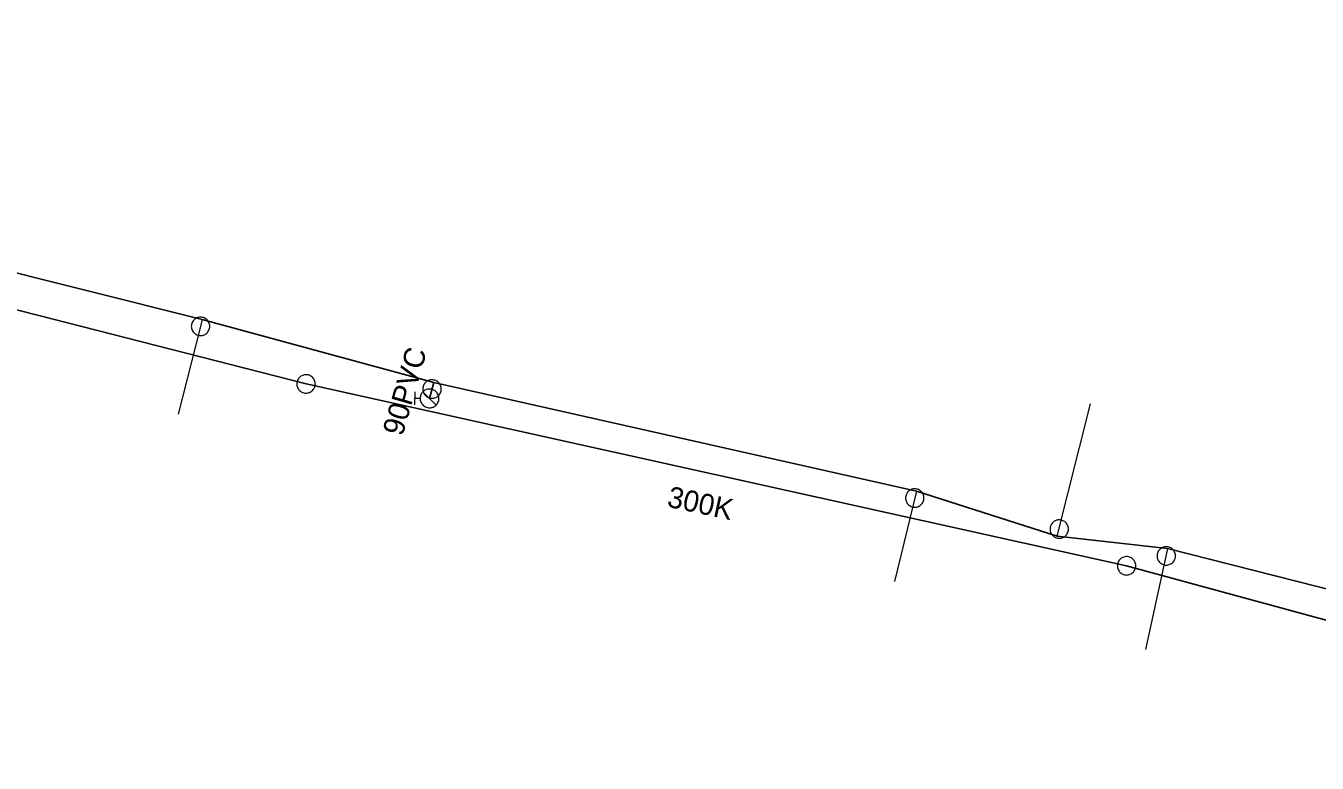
# Model space of a CAD drawing. Extents: x -741806 to -738704, y -1059275 to -1055387.
# Drawn here: x -740232.1 to -740170.7, y -1056858 to -1056822.9 of the extents above; entities that cross this region are included whole.
import ezdxf

# ---------------------------------------------------------------- set-up
doc = ezdxf.new("R2010")
doc.units = 0
doc.header["$LTSCALE"] = 0.4
for name, color, linetype, lineweight in [('2', 7, 'Continuous', 25), ('21', 7, 'Continuous', 13), ('3', 7, 'Continuous', 13), ('50', 7, 'Continuous', 13), ('51', 7, 'Continuous', 13), ('52', 7, 'Continuous', 25)]:
    doc.layers.add(name, color=color, linetype=linetype, lineweight=lineweight)
doc.layers.add('5', color=7, linetype='Continuous')
doc.layers.add('53', color=7, linetype='Continuous')

msp = doc.modelspace()

# ---------------------------------------------------------------- linework, layer by layer
at = {"layer": '2'}
msp.add_lwpolyline([(-740254.32, -1056830.86), (-740218.739, -1056839.96), (-740179.76, -1056848.6), (-740146.01, -1056857.78), (-740138.59, -1056847.639)], dxfattribs=at)
at = {"layer": '21'}
for p, q in [((-740183.054, -1056847.2), (-740181.473, -1056840.899)), ((-740189.741, -1056845.049), (-740190.787, -1056849.345)), ((-740177.82, -1056847.787), (-740178.864, -1056852.575))]:
    msp.add_line(p, q, dxfattribs=at)
msp.add_lwpolyline([(-740223.669, -1056836.908), (-740223.754, -1056837.227), (-740224.82, -1056841.397)], dxfattribs=at)
at = {"layer": '3'}
for points in [[(-740218.314, -1056840.069), (-740218.306, -1056840.024), (-740218.302, -1056839.979), (-740218.302, -1056839.932), (-740218.307, -1056839.888), (-740218.317, -1056839.843), (-740218.332, -1056839.799), (-740218.351, -1056839.758), (-740218.374, -1056839.718), (-740218.402, -1056839.682), (-740218.433, -1056839.648), (-740218.467, -1056839.618), (-740218.505, -1056839.59), (-740218.545, -1056839.569), (-740218.586, -1056839.55), (-740218.63, -1056839.537), (-740218.675, -1056839.527), (-740218.721, -1056839.524), (-740218.766, -1056839.524), (-740218.812, -1056839.529), (-740218.857, -1056839.54), (-740218.9, -1056839.554), (-740218.941, -1056839.573), (-740218.981, -1056839.597), (-740219.018, -1056839.623), (-740219.052, -1056839.655), (-740219.081, -1056839.69), (-740219.108, -1056839.726), (-740219.131, -1056839.767), (-740219.149, -1056839.809), (-740219.162, -1056839.853), (-740219.171, -1056839.897), (-740219.176, -1056839.942), (-740219.175, -1056839.989), (-740219.17, -1056840.035), (-740219.16, -1056840.078), (-740219.146, -1056840.122), (-740219.126, -1056840.163), (-740219.102, -1056840.203), (-740219.075, -1056840.239), (-740219.045, -1056840.273), (-740219.01, -1056840.303), (-740218.973, -1056840.331), (-740218.933, -1056840.353), (-740218.891, -1056840.371), (-740218.847, -1056840.384), (-740218.802, -1056840.394), (-740218.757, -1056840.398), (-740218.711, -1056840.397), (-740218.665, -1056840.392), (-740218.62, -1056840.381), (-740218.577, -1056840.367), (-740218.536, -1056840.348), (-740218.496, -1056840.324), (-740218.46, -1056840.298), (-740218.426, -1056840.266), (-740218.395, -1056840.232), (-740218.369, -1056840.195), (-740218.347, -1056840.154), (-740218.329, -1056840.112), (-740218.315, -1056840.069)], [(-740179.332, -1056848.695), (-740179.325, -1056848.65), (-740179.322, -1056848.605), (-740179.324, -1056848.558), (-740179.331, -1056848.514), (-740179.342, -1056848.469), (-740179.358, -1056848.426), (-740179.379, -1056848.385), (-740179.403, -1056848.346), (-740179.432, -1056848.311), (-740179.464, -1056848.278), (-740179.499, -1056848.249), (-740179.538, -1056848.223), (-740179.578, -1056848.203), (-740179.621, -1056848.185), (-740179.665, -1056848.173), (-740179.71, -1056848.165), (-740179.756, -1056848.163), (-740179.801, -1056848.165), (-740179.847, -1056848.172), (-740179.892, -1056848.184), (-740179.934, -1056848.2), (-740179.974, -1056848.22), (-740180.014, -1056848.245), (-740180.05, -1056848.272), (-740180.082, -1056848.305), (-740180.111, -1056848.341), (-740180.137, -1056848.378), (-740180.158, -1056848.42), (-740180.175, -1056848.462), (-740180.186, -1056848.506), (-740180.194, -1056848.551), (-740180.197, -1056848.596), (-740180.195, -1056848.643), (-740180.188, -1056848.688), (-740180.177, -1056848.732), (-740180.161, -1056848.775), (-740180.14, -1056848.816), (-740180.115, -1056848.855), (-740180.087, -1056848.89), (-740180.055, -1056848.923), (-740180.02, -1056848.952), (-740179.982, -1056848.978), (-740179.941, -1056848.999), (-740179.899, -1056849.016), (-740179.854, -1056849.028), (-740179.809, -1056849.036), (-740179.764, -1056849.039), (-740179.718, -1056849.036), (-740179.672, -1056849.029), (-740179.628, -1056849.017), (-740179.585, -1056849.001), (-740179.544, -1056848.982), (-740179.506, -1056848.956), (-740179.47, -1056848.928), (-740179.437, -1056848.896), (-740179.408, -1056848.86), (-740179.383, -1056848.823), (-740179.361, -1056848.781), (-740179.345, -1056848.739), (-740179.332, -1056848.696)]]:
    msp.add_lwpolyline(points, dxfattribs=at)
at = {"layer": '50'}
for p, q in [((-740213.572, -1056840.342), (-740213.572, -1056840.649)), ((-740213.321, -1056840.649), (-740213.572, -1056840.649)), ((-740213.572, -1056840.957), (-740213.572, -1056840.649)), ((-740212.874, -1056840.649), (-740213.186, -1056840.333)), ((-740212.874, -1056840.649), (-740212.557, -1056840.966))]:
    msp.add_line(p, q, dxfattribs=at)
msp.add_lwpolyline([(-740212.87, -1056840.205), (-740212.919, -1056840.207), (-740212.965, -1056840.212), (-740213.011, -1056840.225), (-740213.054, -1056840.242), (-740213.094, -1056840.261), (-740213.135, -1056840.288), (-740213.17, -1056840.317), (-740213.205, -1056840.35), (-740213.235, -1056840.385), (-740213.259, -1056840.425), (-740213.281, -1056840.466), (-740213.3, -1056840.509), (-740213.31, -1056840.555), (-740213.318, -1056840.601), (-740213.321, -1056840.647), (-740213.318, -1056840.693), (-740213.313, -1056840.738), (-740213.3, -1056840.784), (-740213.283, -1056840.828), (-740213.262, -1056840.871), (-740213.237, -1056840.909), (-740213.208, -1056840.946), (-740213.175, -1056840.979), (-740213.14, -1056841.008), (-740213.1, -1056841.035), (-740213.059, -1056841.057), (-740213.016, -1056841.073), (-740212.97, -1056841.087), (-740212.924, -1056841.092), (-740212.878, -1056841.098), (-740212.83, -1056841.096), (-740212.784, -1056841.088), (-740212.741, -1056841.077), (-740212.695, -1056841.061), (-740212.654, -1056841.039), (-740212.614, -1056841.015), (-740212.579, -1056840.985), (-740212.544, -1056840.953), (-740212.514, -1056840.915), (-740212.49, -1056840.877), (-740212.468, -1056840.834), (-740212.452, -1056840.791), (-740212.438, -1056840.748), (-740212.43, -1056840.699), (-740212.427, -1056840.653), (-740212.43, -1056840.607), (-740212.438, -1056840.561), (-740212.449, -1056840.515), (-740212.465, -1056840.472), (-740212.487, -1056840.429), (-740212.511, -1056840.391), (-740212.541, -1056840.353), (-740212.573, -1056840.321), (-740212.608, -1056840.291), (-740212.649, -1056840.267), (-740212.689, -1056840.243), (-740212.733, -1056840.226), (-740212.778, -1056840.216), (-740212.824, -1056840.208)], close=True, dxfattribs=at)
at = {"layer": '51'}
for points in [[(-740223.753, -1056836.79), (-740223.798, -1056836.791), (-740223.843, -1056836.798), (-740223.888, -1056836.81), (-740223.93, -1056836.826), (-740223.971, -1056836.847), (-740224.01, -1056836.872), (-740224.045, -1056836.901), (-740224.078, -1056836.933), (-740224.106, -1056836.969), (-740224.131, -1056837.007), (-740224.152, -1056837.048), (-740224.169, -1056837.091), (-740224.181, -1056837.135), (-740224.188, -1056837.18), (-740224.19, -1056837.226), (-740224.188, -1056837.272), (-740224.181, -1056837.317), (-740224.169, -1056837.361), (-740224.152, -1056837.404), (-740224.131, -1056837.445), (-740224.106, -1056837.483), (-740224.078, -1056837.519), (-740224.045, -1056837.551), (-740224.01, -1056837.58), (-740223.971, -1056837.605), (-740223.93, -1056837.626), (-740223.888, -1056837.642), (-740223.843, -1056837.654), (-740223.798, -1056837.661), (-740223.752, -1056837.665), (-740223.707, -1056837.662), (-740223.662, -1056837.655), (-740223.617, -1056837.643), (-740223.575, -1056837.627), (-740223.534, -1056837.606), (-740223.495, -1056837.581), (-740223.46, -1056837.552), (-740223.427, -1056837.52), (-740223.399, -1056837.484), (-740223.374, -1056837.446), (-740223.353, -1056837.405), (-740223.336, -1056837.362), (-740223.325, -1056837.318), (-740223.317, -1056837.273), (-740223.315, -1056837.227), (-740223.317, -1056837.181), (-740223.325, -1056837.136), (-740223.336, -1056837.092), (-740223.353, -1056837.049), (-740223.374, -1056837.008), (-740223.399, -1056836.97), (-740223.427, -1056836.934), (-740223.46, -1056836.902), (-740223.495, -1056836.873), (-740223.534, -1056836.848), (-740223.575, -1056836.827), (-740223.617, -1056836.811), (-740223.662, -1056836.799), (-740223.707, -1056836.792), (-740223.752, -1056836.79)], [(-740212.753, -1056839.766), (-740212.798, -1056839.767), (-740212.843, -1056839.774), (-740212.888, -1056839.786), (-740212.93, -1056839.802), (-740212.971, -1056839.823), (-740213.01, -1056839.848), (-740213.045, -1056839.877), (-740213.078, -1056839.909), (-740213.106, -1056839.945), (-740213.131, -1056839.983), (-740213.152, -1056840.024), (-740213.169, -1056840.067), (-740213.181, -1056840.111), (-740213.188, -1056840.156), (-740213.19, -1056840.202), (-740213.188, -1056840.248), (-740213.181, -1056840.293), (-740213.169, -1056840.337), (-740213.152, -1056840.38), (-740213.131, -1056840.421), (-740213.106, -1056840.459), (-740213.078, -1056840.495), (-740213.045, -1056840.527), (-740213.01, -1056840.556), (-740212.971, -1056840.581), (-740212.93, -1056840.602), (-740212.888, -1056840.618), (-740212.843, -1056840.63), (-740212.798, -1056840.637), (-740212.752, -1056840.641), (-740212.707, -1056840.638), (-740212.662, -1056840.631), (-740212.617, -1056840.619), (-740212.575, -1056840.603), (-740212.534, -1056840.582), (-740212.495, -1056840.557), (-740212.46, -1056840.528), (-740212.427, -1056840.496), (-740212.399, -1056840.46), (-740212.374, -1056840.422), (-740212.353, -1056840.381), (-740212.336, -1056840.338), (-740212.325, -1056840.294), (-740212.317, -1056840.249), (-740212.315, -1056840.203), (-740212.317, -1056840.157), (-740212.325, -1056840.112), (-740212.336, -1056840.068), (-740212.353, -1056840.025), (-740212.374, -1056839.984), (-740212.399, -1056839.946), (-740212.427, -1056839.91), (-740212.46, -1056839.878), (-740212.495, -1056839.849), (-740212.534, -1056839.824), (-740212.575, -1056839.803), (-740212.617, -1056839.787), (-740212.662, -1056839.775), (-740212.707, -1056839.768), (-740212.752, -1056839.766)], [(-740189.821, -1056844.944), (-740189.866, -1056844.945), (-740189.911, -1056844.952), (-740189.956, -1056844.964), (-740189.998, -1056844.98), (-740190.039, -1056845.001), (-740190.078, -1056845.026), (-740190.113, -1056845.055), (-740190.146, -1056845.087), (-740190.174, -1056845.123), (-740190.199, -1056845.161), (-740190.22, -1056845.202), (-740190.237, -1056845.245), (-740190.249, -1056845.289), (-740190.256, -1056845.334), (-740190.258, -1056845.38), (-740190.256, -1056845.426), (-740190.249, -1056845.471), (-740190.237, -1056845.515), (-740190.22, -1056845.558), (-740190.199, -1056845.599), (-740190.174, -1056845.637), (-740190.146, -1056845.673), (-740190.113, -1056845.705), (-740190.078, -1056845.734), (-740190.039, -1056845.759), (-740189.998, -1056845.78), (-740189.956, -1056845.796), (-740189.911, -1056845.808), (-740189.866, -1056845.815), (-740189.82, -1056845.819), (-740189.775, -1056845.816), (-740189.73, -1056845.809), (-740189.685, -1056845.797), (-740189.643, -1056845.781), (-740189.602, -1056845.76), (-740189.563, -1056845.735), (-740189.528, -1056845.706), (-740189.495, -1056845.674), (-740189.467, -1056845.638), (-740189.442, -1056845.6), (-740189.421, -1056845.559), (-740189.404, -1056845.516), (-740189.393, -1056845.472), (-740189.385, -1056845.427), (-740189.383, -1056845.381), (-740189.385, -1056845.335), (-740189.393, -1056845.29), (-740189.404, -1056845.246), (-740189.421, -1056845.203), (-740189.442, -1056845.162), (-740189.467, -1056845.124), (-740189.495, -1056845.088), (-740189.528, -1056845.056), (-740189.563, -1056845.027), (-740189.602, -1056845.002), (-740189.643, -1056844.981), (-740189.685, -1056844.965), (-740189.73, -1056844.953), (-740189.775, -1056844.946), (-740189.82, -1056844.944)], [(-740182.957, -1056846.421), (-740183.002, -1056846.422), (-740183.047, -1056846.429), (-740183.092, -1056846.441), (-740183.134, -1056846.457), (-740183.175, -1056846.478), (-740183.214, -1056846.503), (-740183.249, -1056846.532), (-740183.282, -1056846.564), (-740183.31, -1056846.6), (-740183.335, -1056846.638), (-740183.356, -1056846.679), (-740183.373, -1056846.722), (-740183.385, -1056846.766), (-740183.392, -1056846.811), (-740183.394, -1056846.857), (-740183.392, -1056846.903), (-740183.385, -1056846.948), (-740183.373, -1056846.992), (-740183.356, -1056847.035), (-740183.335, -1056847.076), (-740183.31, -1056847.114), (-740183.282, -1056847.15), (-740183.249, -1056847.182), (-740183.214, -1056847.211), (-740183.175, -1056847.236), (-740183.134, -1056847.257), (-740183.092, -1056847.273), (-740183.047, -1056847.285), (-740183.002, -1056847.292), (-740182.956, -1056847.296), (-740182.911, -1056847.293), (-740182.866, -1056847.286), (-740182.821, -1056847.274), (-740182.779, -1056847.258), (-740182.738, -1056847.237), (-740182.699, -1056847.212), (-740182.664, -1056847.183), (-740182.631, -1056847.151), (-740182.603, -1056847.115), (-740182.578, -1056847.077), (-740182.557, -1056847.036), (-740182.54, -1056846.993), (-740182.529, -1056846.949), (-740182.521, -1056846.904), (-740182.519, -1056846.858), (-740182.521, -1056846.812), (-740182.529, -1056846.767), (-740182.54, -1056846.723), (-740182.557, -1056846.68), (-740182.578, -1056846.639), (-740182.603, -1056846.601), (-740182.631, -1056846.565), (-740182.664, -1056846.533), (-740182.699, -1056846.504), (-740182.738, -1056846.479), (-740182.779, -1056846.458), (-740182.821, -1056846.442), (-740182.866, -1056846.43), (-740182.911, -1056846.423), (-740182.956, -1056846.421)], [(-740177.874, -1056847.692), (-740177.919, -1056847.693), (-740177.964, -1056847.7), (-740178.009, -1056847.712), (-740178.051, -1056847.728), (-740178.092, -1056847.749), (-740178.131, -1056847.774), (-740178.166, -1056847.803), (-740178.199, -1056847.835), (-740178.227, -1056847.871), (-740178.252, -1056847.909), (-740178.273, -1056847.95), (-740178.29, -1056847.993), (-740178.302, -1056848.037), (-740178.309, -1056848.082), (-740178.311, -1056848.128), (-740178.309, -1056848.174), (-740178.302, -1056848.219), (-740178.29, -1056848.263), (-740178.273, -1056848.306), (-740178.252, -1056848.347), (-740178.227, -1056848.385), (-740178.199, -1056848.421), (-740178.166, -1056848.453), (-740178.131, -1056848.482), (-740178.092, -1056848.507), (-740178.051, -1056848.528), (-740178.009, -1056848.544), (-740177.964, -1056848.556), (-740177.919, -1056848.563), (-740177.873, -1056848.567), (-740177.828, -1056848.564), (-740177.783, -1056848.557), (-740177.738, -1056848.545), (-740177.696, -1056848.529), (-740177.655, -1056848.508), (-740177.616, -1056848.483), (-740177.581, -1056848.454), (-740177.548, -1056848.422), (-740177.52, -1056848.386), (-740177.495, -1056848.348), (-740177.474, -1056848.307), (-740177.457, -1056848.264), (-740177.446, -1056848.22), (-740177.438, -1056848.175), (-740177.436, -1056848.129), (-740177.438, -1056848.083), (-740177.446, -1056848.038), (-740177.457, -1056847.994), (-740177.474, -1056847.951), (-740177.495, -1056847.91), (-740177.52, -1056847.872), (-740177.548, -1056847.836), (-740177.581, -1056847.804), (-740177.616, -1056847.775), (-740177.655, -1056847.75), (-740177.696, -1056847.729), (-740177.738, -1056847.713), (-740177.783, -1056847.701), (-740177.828, -1056847.694), (-740177.873, -1056847.692)]]:
    msp.add_lwpolyline(points, dxfattribs=at)
at = {"layer": '52'}
msp.add_line((-740212.664, -1056839.887), (-740212.879, -1056840.649), dxfattribs=at)
msp.add_lwpolyline([(-740136.706, -1056857.977), (-740154.291, -1056853.747), (-740177.82, -1056847.787), (-740183.054, -1056847.2), (-740189.741, -1056845.049), (-740212.664, -1056839.887), (-740223.669, -1056836.908), (-740240.309, -1056832.732), (-740261.017, -1056827.78), (-740275.537, -1056822.95)], dxfattribs=at)

# ---------------------------------------------------------------- texts
at = {"layer": '5'}
msp.add_text('300K', height=1, rotation=348, dxfattribs=at).set_placement((-740201.631, -1056845.785))
at = {"layer": '53'}
msp.add_text('90PVC ', height=1, rotation=74, dxfattribs=at).set_placement((-740214.157, -1056842.474))

doc.saveas('drawing.dxf')
